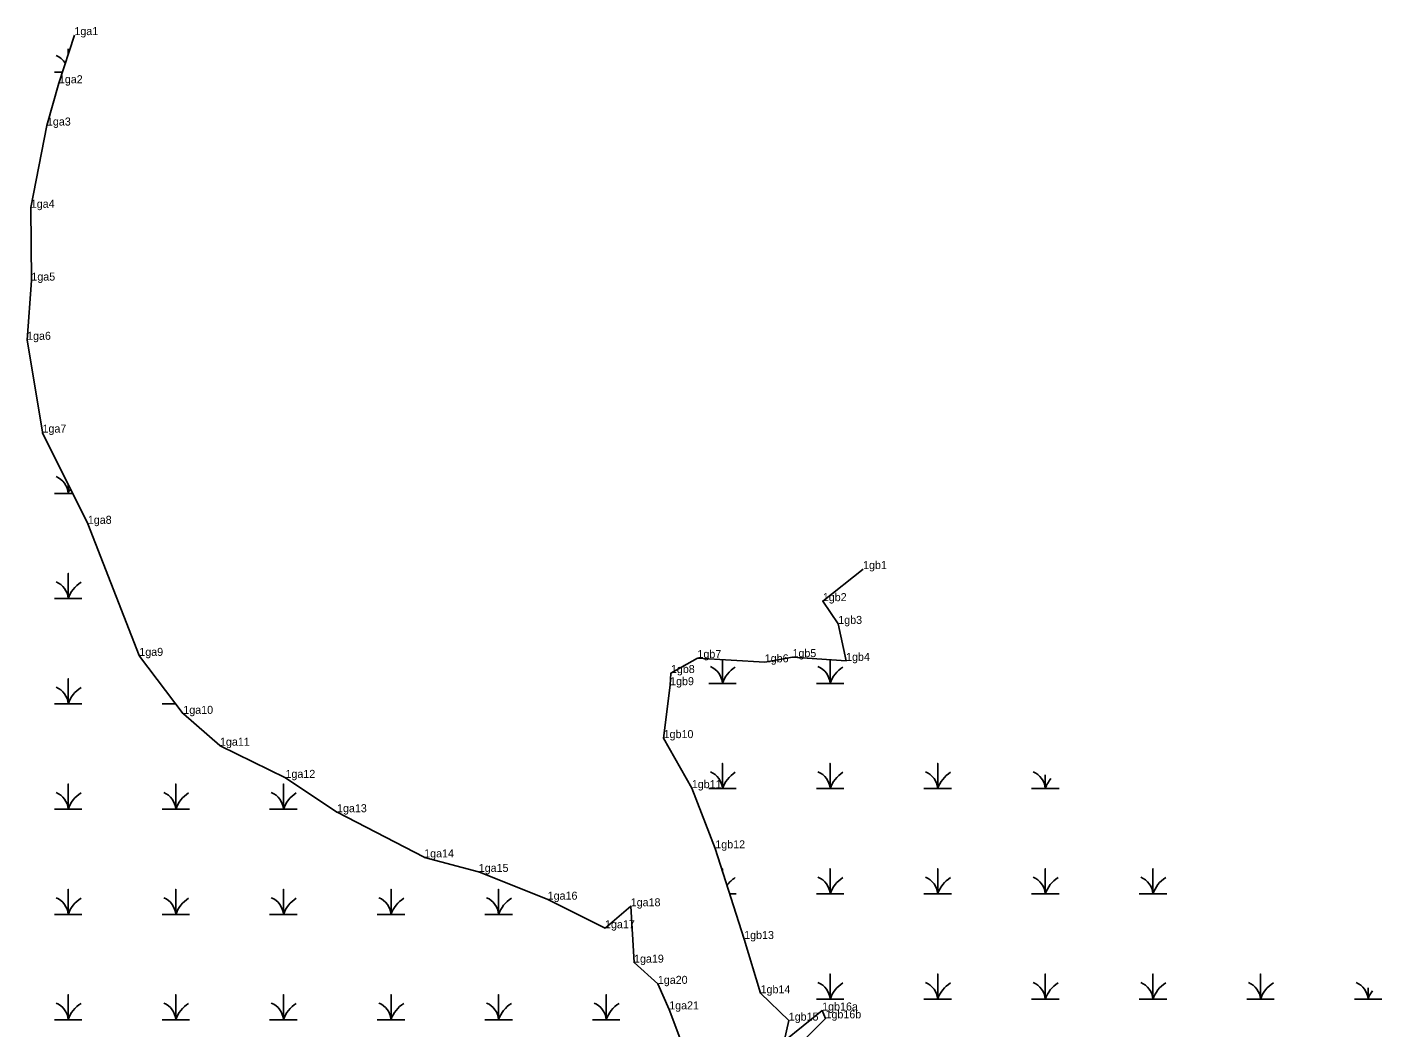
# Model space of a CAD drawing. Extents: x 2072529 to 2268796, y 436423 to 470397.
# Drawn here: x 2076825 to 2077672, y 466864 to 467490 of the extents above; entities that cross this region are included whole.
import ezdxf

# ---------------------------------------------------------------- set-up
doc = ezdxf.new("R2010")
doc.units = 0
for name, color, linetype in [('Exist Environmental Wetland Boundary', 7, 'Continuous'), ('Exist Environmental Wetland Boundary Cogo Comment', 7, 'Continuous'), ('Exist Environmental Wetland Boundary Cogo Point CELL', 7, 'Continuous'), ('Exist Hydro Swamp or Marsh', 7, 'Continuous')]:
    doc.layers.add(name, color=color, linetype=linetype)

msp = doc.modelspace()

# ---------------------------------------------------------------- linework, layer by layer
at = {"layer": 'Exist Environmental Wetland Boundary'}
for p, q in [((2076827.41, 467376.95), (2076837.49, 467428.21)), ((2076827.76, 467331.34), (2076827.39, 467376.75)), ((2076863.01, 467179.39), (2076834.77, 467236.25)), ((2076895.17, 467096.95), (2076863.05, 467179.31)), ((2076922.66, 467060.66), (2076895.31, 467096.71)), ((2076945.53, 467040.76), (2076922.8, 467060.51)), ((2076986.5, 467020.59), (2076945.74, 467040.61)), ((2077018.74, 466999.14), (2076986.61, 467020.52)), ((2077073.15, 466970.93), (2077018.83, 466999.08)), ((2077107.28, 466961.81), (2077073.35, 466970.85))]:
    msp.add_line(p, q, dxfattribs=at)
for points in [[(2076837.51, 467428.29), (2076844.95, 467454.7), (2076854.65, 467484.78)], [(2076834.68, 467236.53), (2076825.08, 467294.33), (2076827.76, 467331.34)], [(2077347.52, 467151.08), (2077322.36, 467131.01), (2077332.02, 467116.79), (2077336.9, 467093.68), (2077303.41, 467096.03), (2077286.07, 467092.8), (2077244.02, 467095.48), (2077227.43, 467086.09), (2077226.94, 467078.5), (2077222.89, 467045.42), (2077240.49, 467014.15), (2077255.18, 466976.51), (2077273.22, 466919.85), (2077283.47, 466885.93), (2077301.08, 466868.86), (2077298.3, 466855.99), (2077321.96, 466875.18), (2077324.06, 466870.28), (2077306.86, 466853.11)], [(2077186.27, 466926.58), (2077150.43, 466944.46), (2077107.4, 466961.77)], [(2077186.27, 466926.58), (2077202.32, 466940.32), (2077204.4, 466905.08), (2077219.26, 466891.84), (2077226.36, 466875.88), (2077237.42, 466846.4)]]:
    msp.add_lwpolyline(points, dxfattribs=at)
for centre, start, end in [((2076838.47, 467428.02), 164.25706, 168.8769), ((2076828.39, 467376.76), 168.8769, 180.46706), ((2076835.67, 467236.69), 189.4325, 206.41134), ((2076862.12, 467178.95), 21.30945, 26.41134), ((2076896.1, 467097.32), 201.30945, 217.18523), ((2076923.46, 467061.26), 217.18523, 229.00609), ((2076946.18, 467041.51), 229.00609, 243.82993), ((2076986.06, 467019.69), 56.35591, 63.82993), ((2077019.29, 466999.97), 236.35591, 242.5974), ((2077073.61, 466971.81), 242.5974, 255.08783), ((2077107.02, 466960.85), 68.08863, 75.08783)]:
    msp.add_arc(centre, 1, start, end, dxfattribs=at)
at = {"layer": 'Exist Environmental Wetland Boundary Cogo Point CELL'}
for p, q in [((2076854.65, 467484.78), (2076854.65, 467484.78)), ((2076844.95, 467454.7), (2076844.95, 467454.7)), ((2076837.5, 467428.25), (2076837.5, 467428.25)), ((2076827.39, 467376.85), (2076827.39, 467376.85)), ((2076827.76, 467331.34), (2076827.76, 467331.34)), ((2076825.08, 467294.33), (2076825.08, 467294.33)), ((2076834.71, 467236.38), (2076834.71, 467236.38)), ((2076863.03, 467179.35), (2076863.03, 467179.35)), ((2077347.52, 467151.08), (2077347.52, 467151.08)), ((2077322.36, 467131.01), (2077322.36, 467131.01)), ((2077332.02, 467116.79), (2077332.02, 467116.79)), ((2076895.22, 467096.82), (2076895.22, 467096.82)), ((2077244.02, 467095.48), (2077244.02, 467095.48)), ((2077286.07, 467092.8), (2077286.07, 467092.8)), ((2077303.41, 467096.03), (2077303.41, 467096.03)), ((2077336.9, 467093.68), (2077336.9, 467093.68)), ((2077227.43, 467086.09), (2077227.43, 467086.09)), ((2077226.94, 467078.5), (2077226.94, 467078.5)), ((2076922.72, 467060.58), (2076922.72, 467060.58)), ((2076945.63, 467040.67), (2076945.63, 467040.67)), ((2077222.89, 467045.42), (2077222.89, 467045.42)), ((2076986.56, 467020.56), (2076986.56, 467020.56)), ((2077240.49, 467014.15), (2077240.49, 467014.15)), ((2077018.79, 466999.11), (2077018.79, 466999.11)), ((2077073.24, 466970.88), (2077073.24, 466970.88)), ((2077255.18, 466976.51), (2077255.18, 466976.51)), ((2077107.34, 466961.8), (2077107.34, 466961.8)), ((2077150.43, 466944.46), (2077150.43, 466944.46)), ((2077202.32, 466940.32), (2077202.32, 466940.32)), ((2077186.27, 466926.58), (2077186.27, 466926.58)), ((2077273.22, 466919.85), (2077273.22, 466919.85)), ((2077204.4, 466905.08), (2077204.4, 466905.08)), ((2077219.26, 466891.84), (2077219.26, 466891.84)), ((2077283.47, 466885.93), (2077283.47, 466885.93)), ((2077226.36, 466875.88), (2077226.36, 466875.88)), ((2077301.08, 466868.86), (2077301.08, 466868.86)), ((2077321.96, 466875.18), (2077321.96, 466875.18)), ((2077324.06, 466870.28), (2077324.06, 466870.28))]:
    msp.add_line(p, q, dxfattribs=at)
at = {"layer": 'Exist Hydro Swamp or Marsh'}
for points in [[(2076850.76, 467472.72), (2076850.76, 467476.14)], [(2076850.76, 467476.14), (2076850.76, 467472.72)], [(2076842.16, 467461.57), (2076847.17, 467461.57)], [(2076842.16, 467198.37), (2076850.76, 467198.37), (2076850.76, 467204.05)], [(2076850.76, 467204.05), (2076850.76, 467198.37), (2076853.58, 467198.37)], [(2076842.16, 467132.57), (2076850.76, 467132.57), (2076850.76, 467148.36), (2076850.76, 467132.57), (2076859.36, 467132.57)], [(2077251.06, 467079.64), (2077259.66, 467079.64), (2077259.66, 467094.48)], [(2077259.66, 467094.48), (2077259.66, 467079.64), (2077268.26, 467079.64)], [(2077318.31, 467079.64), (2077326.91, 467079.64), (2077326.91, 467094.38)], [(2077326.91, 467094.38), (2077326.91, 467079.64), (2077335.51, 467079.64)], [(2076842.16, 467066.77), (2076850.76, 467066.77), (2076850.76, 467082.56), (2076850.76, 467066.77), (2076859.36, 467066.77)], [(2076909.41, 467066.77), (2076918.01, 467066.77), (2076918.01, 467066.78)], [(2076918.01, 467066.78), (2076918.01, 467066.77), (2076918.02, 467066.77)], [(2077251.06, 467013.84), (2077259.66, 467013.84), (2077259.66, 467029.62), (2077259.66, 467013.84), (2077268.26, 467013.84)], [(2077318.31, 467013.84), (2077326.91, 467013.84), (2077326.91, 467029.62), (2077326.91, 467013.84), (2077335.51, 467013.84)], [(2077385.56, 467013.84), (2077394.16, 467013.84), (2077394.16, 467029.62), (2077394.16, 467013.84), (2077402.76, 467013.84)], [(2077452.81, 467013.84), (2077461.41, 467013.84), (2077461.41, 467022.52)], [(2077461.41, 467022.52), (2077461.41, 467013.84), (2077470.01, 467013.84)], [(2076842.16, 467000.97), (2076850.76, 467000.97), (2076850.76, 467016.76), (2076850.76, 467000.97), (2076859.36, 467000.97)], [(2076909.41, 467000.97), (2076918.01, 467000.97), (2076918.01, 467016.76), (2076918.01, 467000.97), (2076926.61, 467000.97)], [(2076976.66, 467000.97), (2076985.26, 467000.97), (2076985.26, 467016.76), (2076985.26, 467000.97), (2076993.86, 467000.97)], [(2077259.66, 466962.43), (2077259.66, 466963.82), (2077259.66, 466962.43)], [(2077318.31, 466948.04), (2077326.91, 466948.04), (2077326.91, 466963.82), (2077326.91, 466948.04), (2077335.51, 466948.04)], [(2077385.56, 466948.04), (2077394.16, 466948.04), (2077394.16, 466963.82), (2077394.16, 466948.04), (2077402.76, 466948.04)], [(2077452.81, 466948.04), (2077461.41, 466948.04), (2077461.41, 466963.82), (2077461.41, 466948.04), (2077470.01, 466948.04)], [(2077520.06, 466948.04), (2077528.66, 466948.04), (2077528.66, 466963.82), (2077528.66, 466948.04), (2077537.26, 466948.04)], [(2076842.16, 466935.17), (2076850.76, 466935.17), (2076850.76, 466950.96), (2076850.76, 466935.17), (2076859.36, 466935.17)], [(2076909.41, 466935.17), (2076918.01, 466935.17), (2076918.01, 466950.96), (2076918.01, 466935.17), (2076926.61, 466935.17)], [(2076976.66, 466935.17), (2076985.26, 466935.17), (2076985.26, 466950.96), (2076985.26, 466935.17), (2076993.86, 466935.17)], [(2077043.91, 466935.17), (2077052.51, 466935.17), (2077052.51, 466950.96), (2077052.51, 466935.17), (2077061.11, 466935.17)], [(2077111.16, 466935.17), (2077119.76, 466935.17), (2077119.76, 466950.96), (2077119.76, 466935.17), (2077128.36, 466935.17)], [(2077264.24, 466948.04), (2077268.26, 466948.04)], [(2077318.31, 466882.24), (2077326.91, 466882.24), (2077326.91, 466898.02), (2077326.91, 466882.24), (2077335.51, 466882.24)], [(2077385.56, 466882.24), (2077394.16, 466882.24), (2077394.16, 466898.02), (2077394.16, 466882.24), (2077402.76, 466882.24)], [(2077452.81, 466882.24), (2077461.41, 466882.24), (2077461.41, 466898.02), (2077461.41, 466882.24), (2077470.01, 466882.24)], [(2077520.06, 466882.24), (2077528.66, 466882.24), (2077528.66, 466898.02), (2077528.66, 466882.24), (2077537.26, 466882.24)], [(2077587.31, 466882.24), (2077595.91, 466882.24), (2077595.91, 466898.02), (2077595.91, 466882.24), (2077604.51, 466882.24)], [(2076842.16, 466869.37), (2076850.76, 466869.37), (2076850.76, 466885.16), (2076850.76, 466869.37), (2076859.36, 466869.37)], [(2076909.41, 466869.37), (2076918.01, 466869.37), (2076918.01, 466885.16), (2076918.01, 466869.37), (2076926.61, 466869.37)], [(2076976.66, 466869.37), (2076985.26, 466869.37), (2076985.26, 466885.16), (2076985.26, 466869.37), (2076993.86, 466869.37)], [(2077043.91, 466869.37), (2077052.51, 466869.37), (2077052.51, 466885.16), (2077052.51, 466869.37), (2077061.11, 466869.37)], [(2077111.16, 466869.37), (2077119.76, 466869.37), (2077119.76, 466885.16), (2077119.76, 466869.37), (2077128.36, 466869.37)], [(2077178.41, 466869.37), (2077187.01, 466869.37), (2077187.01, 466885.16), (2077187.01, 466869.37), (2077195.61, 466869.37)], [(2077654.56, 466882.24), (2077663.16, 466882.24), (2077663.16, 466889.26)], [(2077663.16, 466889.26), (2077663.16, 466882.24), (2077671.76, 466882.24)]]:
    msp.add_lwpolyline(points, dxfattribs=at)
for centre, radius, start, end in [((2076838.5, 467460.69), 12.3, 31.66568, 67.53497), ((2076838.5, 467197.49), 12.3, 4.14034, 67.53497), ((2076869.01, 467192.31), 19.22, 151.74159, 161.62219), ((2076838.5, 467131.69), 12.3, 4.14034, 67.53497), ((2076869.01, 467126.51), 19.22, 122.12745, 161.62219), ((2077247.39, 467078.75), 12.3, 4.14034, 67.53497), ((2077277.9, 467073.58), 19.22, 122.12745, 161.62219), ((2077314.64, 467078.75), 12.3, 4.14034, 67.53497), ((2077345.15, 467073.58), 19.22, 122.12745, 161.62219), ((2076838.5, 467065.89), 12.3, 4.14034, 67.53497), ((2076869.01, 467060.71), 19.22, 122.12745, 161.62219), ((2076936.26, 467060.71), 19.22, 161.60502, 161.62219), ((2076905.75, 467065.89), 12.3, 4.14034, 4.18095), ((2077247.39, 467012.95), 12.3, 4.14034, 67.53497), ((2077277.9, 467007.78), 19.22, 122.12745, 161.62219), ((2077314.64, 467012.95), 12.3, 4.14034, 67.53497), ((2077345.15, 467007.78), 19.22, 122.12745, 161.62219), ((2077381.89, 467012.95), 12.3, 4.14034, 67.53497), ((2077412.4, 467007.78), 19.22, 122.12745, 161.62219), ((2077449.14, 467012.95), 12.3, 4.14034, 67.53497), ((2077479.65, 467007.78), 19.22, 139.8776, 161.62219), ((2076838.5, 467000.09), 12.3, 4.14034, 67.53497), ((2076869.01, 466994.91), 19.22, 122.12745, 161.62219), ((2076905.75, 467000.09), 12.3, 4.14034, 67.53497), ((2076936.26, 466994.91), 19.22, 122.12745, 161.62219), ((2076973, 467000.09), 12.3, 4.14034, 67.53497), ((2077003.51, 466994.91), 19.22, 122.12745, 161.62219), ((2077277.9, 466941.98), 19.22, 122.12745, 143.20617), ((2077314.64, 466947.15), 12.3, 4.14034, 67.53497), ((2077345.15, 466941.98), 19.22, 122.12745, 161.62219), ((2077381.89, 466947.15), 12.3, 4.14034, 67.53497), ((2077412.4, 466941.98), 19.22, 122.12745, 161.62219), ((2077449.14, 466947.15), 12.3, 4.14034, 67.53497), ((2077479.65, 466941.98), 19.22, 122.12745, 161.62219), ((2077516.39, 466947.15), 12.3, 4.14034, 67.53497), ((2077546.9, 466941.98), 19.22, 122.12745, 161.62219), ((2076838.5, 466934.29), 12.3, 4.14034, 67.53497), ((2076869.01, 466929.11), 19.22, 122.12745, 161.62219), ((2076905.75, 466934.29), 12.3, 4.14034, 67.53497), ((2076936.26, 466929.11), 19.22, 122.12745, 161.62219), ((2076973, 466934.29), 12.3, 4.14034, 67.53497), ((2077003.51, 466929.11), 19.22, 122.12745, 161.62219), ((2077040.25, 466934.29), 12.3, 4.14034, 67.53497), ((2077070.76, 466929.11), 19.22, 122.12745, 161.62219), ((2077107.5, 466934.29), 12.3, 4.14034, 67.53497), ((2077138.01, 466929.11), 19.22, 122.12745, 161.62219), ((2077314.64, 466881.35), 12.3, 4.14034, 67.53497), ((2077345.15, 466876.18), 19.22, 122.12745, 161.62219), ((2077381.89, 466881.35), 12.3, 4.14034, 67.53497), ((2077412.4, 466876.18), 19.22, 122.12745, 161.62219), ((2077449.14, 466881.35), 12.3, 4.14034, 67.53497), ((2077479.65, 466876.18), 19.22, 122.12745, 161.62219), ((2077516.39, 466881.35), 12.3, 4.14034, 67.53497), ((2077546.9, 466876.18), 19.22, 122.12745, 161.62219), ((2077583.64, 466881.35), 12.3, 4.14034, 67.53497), ((2077614.15, 466876.18), 19.22, 122.12745, 161.62219), ((2077650.89, 466881.35), 12.3, 4.14034, 67.53497), ((2077681.4, 466876.18), 19.22, 143.97685, 161.62219), ((2076838.5, 466868.49), 12.3, 4.14034, 67.53497), ((2076869.01, 466863.31), 19.22, 122.12745, 161.62219), ((2076905.75, 466868.49), 12.3, 4.14034, 67.53497), ((2076936.26, 466863.31), 19.22, 122.12745, 161.62219), ((2076973, 466868.49), 12.3, 4.14034, 67.53497), ((2077003.51, 466863.31), 19.22, 122.12745, 161.62219), ((2077040.25, 466868.49), 12.3, 4.14034, 67.53497), ((2077070.76, 466863.31), 19.22, 122.12745, 161.62219), ((2077107.5, 466868.49), 12.3, 4.14034, 67.53497), ((2077138.01, 466863.31), 19.22, 122.12745, 161.62219), ((2077174.75, 466868.49), 12.3, 4.14034, 67.53497), ((2077205.26, 466863.31), 19.22, 122.12745, 161.62219)]:
    msp.add_arc(centre, radius, start, end, dxfattribs=at)

# ---------------------------------------------------------------- texts
at = {"layer": 'Exist Environmental Wetland Boundary Cogo Comment'}
for s, p in [('1ga1', (2076854.65, 467484.78)), ('1ga2', (2076844.95, 467454.7)), ('1ga3', (2076837.5, 467428.25)), ('1ga4', (2076827.39, 467376.85)), ('1ga5', (2076827.76, 467331.34)), ('1ga6', (2076825.08, 467294.33)), ('1ga7', (2076834.71, 467236.38)), ('1ga8', (2076863.03, 467179.35)), ('1gb1', (2077347.52, 467151.08)), ('1gb2', (2077322.36, 467131.01)), ('1gb3', (2077332.02, 467116.79)), ('1ga9', (2076895.22, 467096.82)), ('1gb7', (2077244.02, 467095.48)), ('1gb6', (2077286.07, 467092.8)), ('1gb5', (2077303.41, 467096.03)), ('1gb4', (2077336.9, 467093.68)), ('1gb8', (2077227.43, 467086.09)), ('1gb9', (2077226.94, 467078.5)), ('1ga10', (2076922.72, 467060.58)), ('1ga11', (2076945.63, 467040.67)), ('1gb10', (2077222.89, 467045.42)), ('1ga12', (2076986.56, 467020.56)), ('1gb11', (2077240.49, 467014.15)), ('1ga13', (2077018.79, 466999.11)), ('1gb12', (2077255.18, 466976.51)), ('1ga14', (2077073.24, 466970.88)), ('1ga15', (2077107.34, 466961.8)), ('1ga16', (2077150.43, 466944.46)), ('1ga18', (2077202.32, 466940.32)), ('1ga17', (2077186.27, 466926.58)), ('1gb13', (2077273.22, 466919.85)), ('1ga19', (2077204.4, 466905.08)), ('1ga20', (2077219.26, 466891.84)), ('1gb14', (2077283.47, 466885.93)), ('1ga21', (2077226.36, 466875.88)), ('1gb16a', (2077321.96, 466875.18)), ('1gb15', (2077301.08, 466868.86)), ('1gb16b', (2077324.06, 466870.28))]:
    msp.add_text(s, height=5, dxfattribs=at).set_placement(p)

doc.saveas('drawing.dxf')
